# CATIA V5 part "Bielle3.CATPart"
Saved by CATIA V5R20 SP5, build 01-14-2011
Part number: Bielle3
Publications: "Longueur_Bielle3"
Bounding box of the stored display mesh (mm): x -10 to 10, y -140 to 135, z -15 to 15
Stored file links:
  F:\IAO\Projet_IAO5.0\Bielle3.CATPart
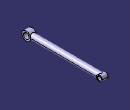
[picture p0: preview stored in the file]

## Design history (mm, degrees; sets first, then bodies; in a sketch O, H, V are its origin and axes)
Parameters
  Longueur_Bielle3 = 250 mm
Body1 (main body)
  Sketch1 on yz-plane, origin (0, 0, 0), H (0, 1, 0), V (0, 0, 1)
    circle A1 centre (-125, 0) radius 10
    point P1 (-125, 0)
    circle A2 centre (-125, 0) radius 15
    circle A3 centre (125, 0) radius 10
    point P2 (125, 0)
    circle A4 centre (125, 0) radius 7
    radius A1 = 10
    radius A2 = 15
    radius A3 = 10
    radius A4 = 7
    distance P1 P2 = 250 {= Longueur_Bielle3}
    distance O P2 = 125 {= Longueur_Bielle3 /2}
    coincidence: P1 H, P2 H
  Pad1: profile Sketch1, direction (1, 0, 0), length 10, mirrored extent
  Sketch2 on zx-plane, origin (0, 0, 0), H (-1, 0, 0), V (0, 0, 1)
    circle A1 centre (0, 0) radius 10
    radius A1 = 10
  Pad2: profile Sketch2, direction (0, 1, 0), up to face of Pad1 from Sketch1.A3, opposite side up to face of Pad1 from Sketch1.A2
